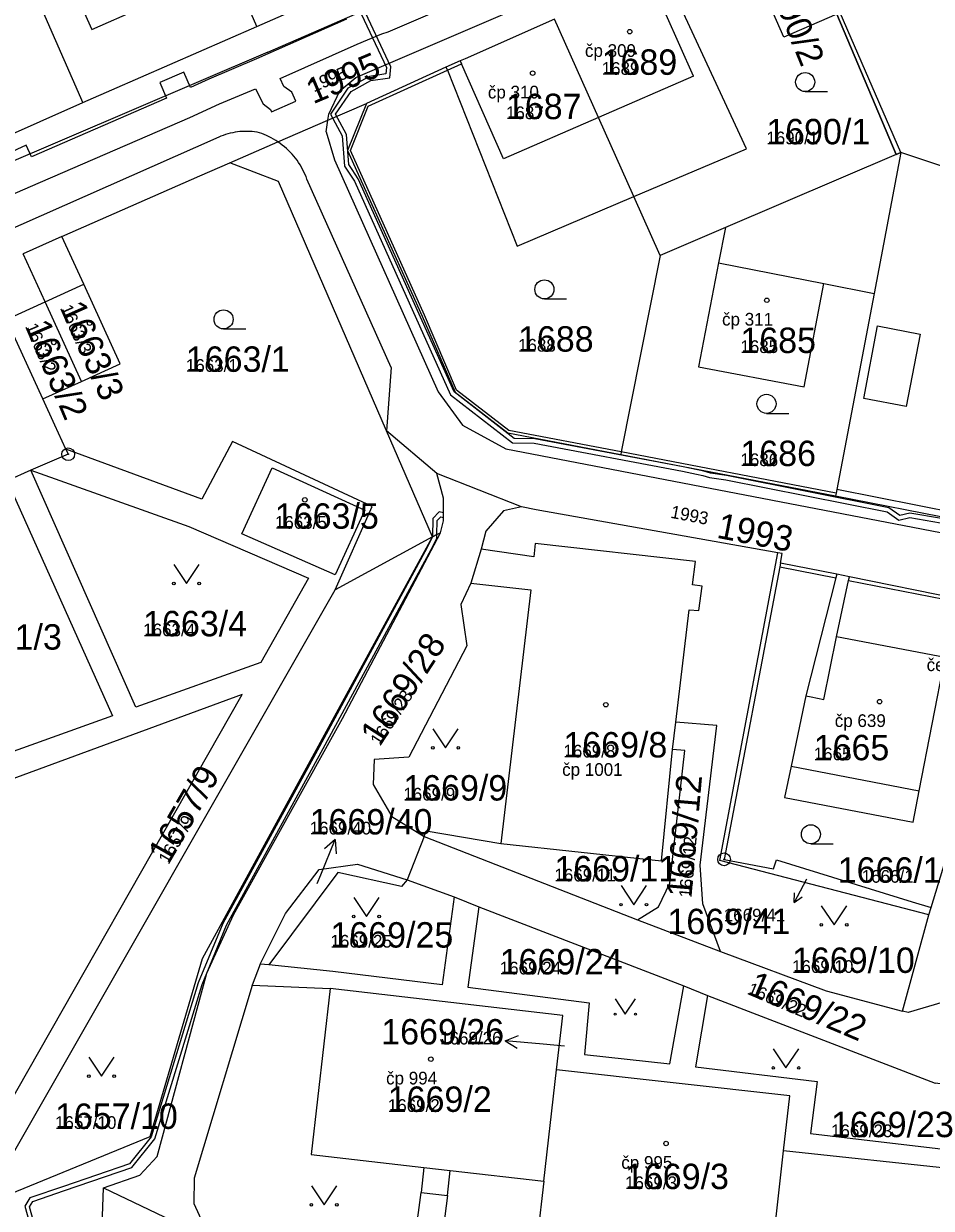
# Model space of a CAD drawing. Extents: x -763628 to -761565, y -976033 to -973833.
# Drawn here: x -762607.2 to -762535.7, y -975162.3 to -975069 of the extents above; entities that cross this region are included whole.
import ezdxf

# ---------------------------------------------------------------- set-up
doc = ezdxf.new("R2010")
doc.units = 0
for name, color, linetype in [('KN_cisla parcel 1000', 7, 'Continuous'), ('KN_cisla parcel 500', 7, 'Continuous'), ('KN_cisla parcel znacky', 7, 'Continuous'), ('KN_cisla popisna 500', 7, 'Continuous'), ('KN_hranice parcel', 7, 'Continuous'), ('KN_vecna bremena', 7, 'Continuous'), ('KN_vnitrni kresba parcel', 7, 'Continuous'), ('KN_znacky bodu BP', 7, 'Continuous'), ('KN_znacky budov', 7, 'Continuous'), ('KN_znacky kultur', 7, 'Continuous')]:
    doc.layers.add(name, color=color, linetype=linetype)

msp = doc.modelspace()

# ---------------------------------------------------------------- linework, layer by layer
at = {"layer": 'KN_cisla parcel znacky'}
for p, q in [((-762583.77, -975136.04), (-762582.646, -975133.258)), ((-762582.646, -975133.258), (-762583.485, -975133.998)), ((-762582.646, -975133.258), (-762582.557, -975134.374)), ((-762584.05, -975136.72), (-762583.77, -975136.04)), ((-762545.56, -975136.44), (-762546.504, -975138.215)), ((-762545.55, -975136.38), (-762545.56, -975136.44)), ((-762546.504, -975138.215), (-762546.485, -975137.465)), ((-762546.504, -975138.215), (-762545.893, -975137.78)), ((-762569.26, -975149.098), (-762568.218, -975148.687)), ((-762566.27, -975149.36), (-762569.26, -975149.098)), ((-762569.26, -975149.098), (-762568.306, -975149.685)), ((-762564.58, -975149.52), (-762566.27, -975149.36))]:
    msp.add_line(p, q, dxfattribs=at)
at = {"layer": 'KN_hranice parcel'}
for p, q in [((-762588.8, -975069.25), (-762599.99, -975043.58)), ((-762588.8, -975069.25), (-762572.25, -975062)), ((-762538.48, -975079.34), (-762543.16, -975068.29)), ((-762602.49, -975075.24), (-762588.8, -975069.25)), ((-762573.92, -975072.46), (-762580.18, -975075.31)), ((-762620.3, -975083.16), (-762602.49, -975075.24)), ((-762538.48, -975079.34), (-762551.93, -975085.09)), ((-762538.11, -975079.18), (-762540.22, -975090.27)), ((-762538.11, -975079.18), (-762538.48, -975079.34)), ((-762527.5, -975082.74), (-762538.11, -975079.18)), ((-762587.09, -975081.47), (-762590.94, -975079.99)), ((-762578.59, -975101.09), (-762587.09, -975081.47)), ((-762557.07, -975087.28), (-762559.14, -975082.65)), ((-762551.93, -975085.09), (-762557.07, -975087.28)), ((-762604.14, -975085.78), (-762607.19, -975087.14)), ((-762605.64, -975098.58), (-762602.6, -975097.19)), ((-762574.63, -975104.45), (-762578.59, -975101.09)), ((-762560.17, -975102.94), (-762543.26, -975106.2)), ((-762567.98, -975107.06), (-762574.63, -975104.45)), ((-762543.26, -975106.2), (-762527.46, -975109.33)), ((-762574.98, -975109.43), (-762582.65, -975113.61)), ((-762574.36, -975109.12), (-762574.98, -975109.43)), ((-762571.14, -975110.39), (-762571.95, -975113.09)), ((-762543.17, -975112.38), (-762547.58, -975111.51)), ((-762542.17, -975112.58), (-762543.17, -975112.38)), ((-762532.74, -975114.51), (-762542.17, -975112.58)), ((-762556.1, -975126.16), (-762555.82, -975124.01)), ((-762535.74, -975138.61), (-762532.33, -975127.36)), ((-762575.64, -975133.02), (-762576.98, -975136.42)), ((-762575.64, -975133.02), (-762558.84, -975139.58)), ((-762576.98, -975136.42), (-762573.28, -975137.78)), ((-762573.28, -975137.78), (-762571.34, -975138.57)), ((-762571.34, -975138.57), (-762555.21, -975144.77)), ((-762538, -975146.76), (-762535.92, -975139.19)), ((-762535.92, -975139.19), (-762535.74, -975138.61)), ((-762558.84, -975139.58), (-762552.31, -975142.08)), ((-762588.53, -975143.06), (-762589.17, -975144.72)), ((-762587.87, -975143.13), (-762588.53, -975143.06)), ((-762589.17, -975144.72), (-762583.02, -975145)), ((-762555.21, -975144.77), (-762553.34, -975145.55)), ((-762553.34, -975145.55), (-762535.42, -975152.45)), ((-762566.23, -975160.16), (-762565.22, -975151.39)), ((-762548.34, -975166.58), (-762547.35, -975157.76)), ((-762528.85, -975159.77), (-762547.35, -975157.76)), ((-762601.07, -975165.85), (-762600.86, -975160.68)), ((-762600.86, -975160.68), (-762591.67, -975165.07)), ((-762577.47, -975173.2), (-762575.87, -975161.05)), ((-762575.87, -975161.05), (-762573.8, -975161.29))]:
    msp.add_line(p, q, dxfattribs=at)
for points in [[(-762602.49, -975075.24), (-762602.65, -975074.88), (-762615.7, -975045.16)], [(-762594.38, -975066.21), (-762597.89, -975058.78), (-762599.15, -975056.11), (-762606.37, -975059.33), (-762605.03, -975062.29), (-762604.38, -975063.72), (-762605.61, -975064.27), (-762604.97, -975065.69), (-762604.22, -975067.35), (-762602.99, -975066.8), (-762601.78, -975069.49), (-762594.38, -975066.21)], [(-762543.16, -975068.29), (-762547.34, -975070.1), (-762549.45, -975065.25), (-762550.63, -975065.76), (-762551.03, -975064.81), (-762549.86, -975064.3), (-762550.64, -975062.55), (-762550.74, -975062.32)], [(-762559.14, -975082.65), (-762550.28, -975078.88), (-762555.4, -975067.8), (-762554.75, -975067.51), (-762555.94, -975064.83), (-762556.04, -975064.6)], [(-762565.38, -975068.69), (-762572.42, -975071.8), (-762572.79, -975071.96), (-762573.92, -975072.46)], [(-762559.14, -975082.65), (-762561.92, -975076.42), (-762565.38, -975068.69)], [(-762573.92, -975072.46), (-762573.81, -975072.69), (-762568.32, -975086.56), (-762559.14, -975082.65)], [(-762590.94, -975079.99), (-762587.14, -975078.34), (-762583.21, -975076.63), (-762580.18, -975075.31)], [(-762580.18, -975075.31), (-762581.66, -975079.03), (-762575.79, -975092.06), (-762573.2, -975098.04), (-762569.06, -975101.24), (-762560.17, -975102.94)], [(-762604.14, -975085.78), (-762593.28, -975081), (-762590.94, -975079.99)], [(-762551.93, -975085.09), (-762552.47, -975087.86), (-762554.05, -975096.04), (-762545.74, -975097.63), (-762544.18, -975089.49), (-762540.22, -975090.27)], [(-762602.6, -975097.19), (-762599.56, -975095.8), (-762602.42, -975089.55), (-762604.14, -975085.78)], [(-762602.6, -975097.19), (-762605.46, -975090.94), (-762607.19, -975087.14)], [(-762557.07, -975087.28), (-762560.13, -975102.74), (-762560.17, -975102.94)], [(-762605.64, -975098.58), (-762608.5, -975092.33), (-762610.25, -975088.49)], [(-762540.22, -975090.27), (-762543.17, -975105.71), (-762543.22, -975106), (-762543.26, -975106.2)], [(-762603.83, -975102.53), (-762604.7, -975100.63), (-762605.64, -975098.58)], [(-762582.65, -975113.61), (-762579.74, -975107.03), (-762590.71, -975101.93), (-762593.12, -975106.47), (-762603.83, -975102.53)], [(-762603.83, -975102.53), (-762603.65, -975102.93), (-762606.58, -975104.18), (-762608.46, -975105.01)], [(-762606.58, -975104.18), (-762594.16, -975108.62), (-762584.74, -975112.69), (-762588.48, -975119.33), (-762598.32, -975122.84), (-762606.58, -975104.18)], [(-762589.98, -975109.2), (-762587.6, -975103.99), (-762580.31, -975107.33), (-762582.63, -975112.43), (-762589.98, -975109.2)], [(-762574.36, -975109.12), (-762574.11, -975108.17), (-762574.12, -975106.38), (-762574.63, -975104.45)], [(-762608.46, -975105.01), (-762600.17, -975123.53), (-762610.99, -975127.4), (-762612.67, -975125.75)], [(-762567.98, -975107.06), (-762569.4, -975107.38), (-762570.77, -975108.98), (-762571.14, -975110.39)], [(-762547.79, -975110.69), (-762566.82, -975107.3), (-762567.98, -975107.06)], [(-762632.68, -975171.16), (-762632.45, -975171.07), (-762627.1, -975168.88), (-762597.19, -975156.63), (-762593.08, -975142.62), (-762574.98, -975109.43)], [(-762600.86, -975160.68), (-762598.01, -975159.67), (-762596.66, -975158.21), (-762592.74, -975143.77), (-762590.64, -975139.19), (-762582.07, -975123.74), (-762574.36, -975109.12)], [(-762555.82, -975124.01), (-762554.78, -975115.18), (-762554.02, -975115.23), (-762553.76, -975113.32), (-762554.53, -975113.22), (-762554.29, -975111.37), (-762566.89, -975109.96), (-762567.01, -975111.01), (-762571.14, -975110.39)], [(-762535.92, -975139.19), (-762552.37, -975134.92), (-762547.79, -975110.69)], [(-762547.58, -975111.51), (-762547.47, -975110.75), (-762547.79, -975110.69)], [(-762547.58, -975111.51), (-762547.64, -975111.8), (-762552.03, -975134.82), (-762548.14, -975135.56), (-762547.92, -975134.87), (-762537.22, -975138.16), (-762535.74, -975138.61)], [(-762571.95, -975113.09), (-762572.74, -975114.76), (-762572.29, -975118.02), (-762576.83, -975126.78), (-762579.56, -975126.96), (-762579.64, -975128.92), (-762578.18, -975131.45), (-762575.64, -975133.02)], [(-762571.95, -975113.09), (-762567.23, -975113.59), (-762569.61, -975133.56)], [(-762543.17, -975112.38), (-762543.24, -975112.67), (-762545.61, -975121.95), (-762546.76, -975127.48), (-762547.27, -975129.94), (-762537.16, -975131.9), (-762536.68, -975129.43), (-762534.63, -975118.92), (-762543.18, -975117.3), (-762542.23, -975112.87), (-762542.17, -975112.58)], [(-762634.24, -975155.87), (-762623.43, -975164.98), (-762608.7, -975159.22), (-762582.65, -975113.61)], [(-762632.02, -975155.16), (-762623.17, -975162.78), (-762610.31, -975157.57), (-762589.96, -975121.84), (-762614.1, -975130.7)], [(-762552.31, -975142.08), (-762553.7, -975138.33), (-762553.91, -975135.28), (-762552.59, -975124.29), (-762555.82, -975124.01)], [(-762569.61, -975133.56), (-762556.95, -975134.95), (-762556.1, -975126.16)], [(-762558.84, -975139.58), (-762557.19, -975138.56), (-762556.3, -975136.7), (-762555.12, -975126.25), (-762556.1, -975126.16)], [(-762519.59, -975130.51), (-762520.25, -975132.74), (-762532.03, -975144.17), (-762534.8, -975146.05), (-762537.54, -975146.88), (-762538, -975146.76)], [(-762575.64, -975133.02), (-762575.48, -975132.58), (-762569.61, -975133.56)], [(-762588.53, -975143.06), (-762586.54, -975139.09), (-762583.91, -975135.61), (-762580.88, -975135.21), (-762576.98, -975136.42)], [(-762576.98, -975136.42), (-762577.41, -975136.95), (-762582.42, -975135.86), (-762587.87, -975143.13)], [(-762573.28, -975137.78), (-762574.23, -975144.7), (-762582.82, -975143.64), (-762587.87, -975143.13)], [(-762571.34, -975138.57), (-762572.21, -975144.89), (-762562.66, -975146.11), (-762563.03, -975150.18), (-762556.3, -975150.93), (-762555.21, -975144.77)], [(-762552.31, -975142.08), (-762544.01, -975145.16), (-762538, -975146.76)], [(-762589.17, -975144.72), (-762589.25, -975145.02), (-762593.73, -975159.93), (-762593.75, -975161.9), (-762592.76, -975164.08)], [(-762583.02, -975145), (-762584.52, -975158.06), (-762575.65, -975159.08), (-762575.87, -975161.05)], [(-762565.22, -975151.39), (-762564.73, -975147.1), (-762583.02, -975145)], [(-762553.34, -975145.55), (-762554.27, -975151.16), (-762544.7, -975152.32), (-762545.22, -975156.41), (-762533.42, -975157.8), (-762532.89, -975152.76), (-762535.42, -975152.45)], [(-762547.35, -975157.76), (-762546.87, -975153.44), (-762565.22, -975151.39)], [(-762573.8, -975161.29), (-762573.58, -975159.32), (-762566.23, -975160.16)], [(-762566.23, -975160.16), (-762566.72, -975164.45), (-762557.8, -975165.48), (-762558.03, -975167.47)], [(-762573.8, -975161.29), (-762575.18, -975172.07), (-762559.12, -975179), (-762558.03, -975167.47)]]:
    msp.add_lwpolyline(points, dxfattribs=at)
at = {"layer": 'KN_vecna bremena'}
for points in [[(-762546.26, -975060.4), (-762546.52, -975060.51), (-762546.42, -975060.74), (-762543.16, -975068.29), (-762538.48, -975079.34), (-762538.11, -975079.18), (-762542.89, -975068.17), (-762546.16, -975060.63)], [(-762574.64, -975109.26), (-762574.62, -975108.14), (-762574.33, -975107.85), (-762574.11, -975107.9), (-762574.11, -975107.55), (-762574.45, -975107.47), (-762574.96, -975108), (-762574.98, -975109.43)], [(-762605.5, -975167.74), (-762605.18, -975167.61), (-762606.69, -975162.17), (-762606.44, -975161.75), (-762603.93, -975160.9), (-762598.63, -975159.07), (-762596.82, -975156.83), (-762593.1, -975144.67), (-762592.74, -975143.77), (-762591.18, -975140.01), (-762583.58, -975126.09), (-762575.09, -975110.43), (-762574.64, -975109.53), (-762574.64, -975109.26), (-762574.98, -975109.43), (-762575.39, -975110.27), (-762583.88, -975125.93), (-762591.48, -975139.87), (-762593.42, -975144.55), (-762597.12, -975156.67), (-762598.83, -975158.79), (-762604.03, -975160.58), (-762606.66, -975161.47), (-762607.05, -975162.13)]]:
    msp.add_lwpolyline(points, close=True, dxfattribs=at)
for points in [[(-762620.32, -975087.8), (-762606.61, -975081.85), (-762594.08, -975076.41), (-762591.74, -975075.34), (-762588.91, -975074.16), (-762588.31, -975075.35), (-762587.72, -975075.79), (-762587.64, -975075.98), (-762585.73, -975075.14), (-762586.04, -975074.43), (-762586.67, -975073.97), (-762586.98, -975073.34), (-762580.9, -975070.65), (-762578.97, -975069.83), (-762578.46, -975069.68), (-762568.97, -975065.59)], [(-762580.79, -975067.8), (-762578.61, -975072.48), (-762578.66, -975072.99), (-762579.95, -975073.2), (-762581.63, -975074.1), (-762583, -975076.15), (-762582.1, -975077.87), (-762581.91, -975080.25), (-762581.58, -975080.72), (-762581.12, -975081.42), (-762573.56, -975098.24), (-762568.68, -975102.03)], [(-762539.06, -975107.14), (-762551.84, -975104.6), (-762553.09, -975104.42), (-762553.62, -975104.27), (-762554.13, -975104.15), (-762555.24, -975103.92), (-762566.93, -975101.72), (-762568.56, -975101.69), (-762573.28, -975098.02), (-762580.82, -975081.26), (-762581.3, -975080.52), (-762581.57, -975080.13), (-762581.76, -975077.77), (-762582.6, -975076.17), (-762581.39, -975074.36), (-762579.83, -975073.52), (-762578.34, -975073.29), (-762578.27, -975072.42), (-762580.43, -975067.78)], [(-762581.76, -975068.67), (-762588.83, -975071.79), (-762592.58, -975073.4), (-762594.03, -975074.06), (-762594.56, -975072.84), (-762596.44, -975073.66), (-762595.9, -975074.9), (-762606.53, -975079.51), (-762606.95, -975078.6), (-762608.81, -975079.46)], [(-762568.68, -975102.03), (-762566.97, -975102.06), (-762555.3, -975104.26), (-762554.21, -975104.49), (-762553.7, -975104.59), (-762553.17, -975104.76), (-762551.9, -975104.94), (-762539.2, -975107.46), (-762538.28, -975108.11), (-762537.41, -975107.92), (-762534.99, -975108.32)], [(-762534.93, -975107.98), (-762537.41, -975107.58), (-762538.2, -975107.75), (-762539.06, -975107.14)]]:
    msp.add_lwpolyline(points, dxfattribs=at)
at = {"layer": 'KN_vnitrni kresba parcel'}
for p, q in [((-762587.93, -975071.28), (-762528.01, -975045.1)), ((-762581, -975073.28), (-762530.07, -975051.35)), ((-762554.43, -975073.16), (-762556.6, -975068.35)), ((-762587.93, -975071.28), (-762619.58, -975084.8)), ((-762573.81, -975072.69), (-762572.69, -975072.19)), ((-762572.79, -975071.96), (-762572.69, -975072.19)), ((-762569.39, -975079.68), (-762572.69, -975072.19)), ((-762580.05, -975075.52), (-762573.81, -975072.69)), ((-762554.43, -975073.16), (-762561.92, -975076.42)), ((-762582.27, -975074.33), (-762581, -975073.28)), ((-762583.14, -975076.15), (-762582.27, -975074.33)), ((-762581.44, -975079.03), (-762580.05, -975075.52)), ((-762583.34, -975077.54), (-762583.21, -975076.63)), ((-762583.21, -975076.63), (-762583.14, -975076.15)), ((-762561.92, -975076.42), (-762569.39, -975079.68)), ((-762583.34, -975077.54), (-762582.7, -975079.74)), ((-762591.8, -975077.98), (-762691.91, -975122.23)), ((-762575.61, -975091.98), (-762581.44, -975079.03)), ((-762582.7, -975079.74), (-762574.53, -975098.02)), ((-762578.22, -975096.1), (-762584.86, -975081.27)), ((-762552.47, -975087.86), (-762544.18, -975089.49)), ((-762605.46, -975090.94), (-762602.42, -975089.55)), ((-762608.5, -975092.33), (-762605.46, -975090.94)), ((-762573.08, -975097.88), (-762575.61, -975091.98)), ((-762541.04, -975098.53), (-762539.95, -975092.83)), ((-762539.95, -975092.83), (-762536.6, -975093.47)), ((-762536.6, -975093.47), (-762537.69, -975099.16)), ((-762578.22, -975096.1), (-762578.59, -975101.09)), ((-762574.53, -975098.02), (-762572.61, -975100.65)), ((-762568.98, -975101.06), (-762573.08, -975097.88)), ((-762537.69, -975099.16), (-762541.04, -975098.53)), ((-762574.98, -975109.43), (-762578.59, -975101.09)), ((-762572.61, -975100.65), (-762569.22, -975102.51)), ((-762560.13, -975102.74), (-762568.98, -975101.06)), ((-762569.22, -975102.51), (-762527.62, -975110.52)), ((-762543.22, -975106), (-762560.13, -975102.74)), ((-762527.32, -975108.85), (-762543.17, -975105.71)), ((-762547.64, -975111.8), (-762543.24, -975112.67)), ((-762542.23, -975112.87), (-762532.78, -975114.72)), ((-762544.17, -975122.24), (-762543.18, -975117.3)), ((-762545.61, -975121.95), (-762545.19, -975122.03)), ((-762545.19, -975122.03), (-762544.17, -975122.24)), ((-762546.76, -975127.48), (-762536.68, -975129.43)), ((-762575.65, -975159.08), (-762573.58, -975159.32))]:
    msp.add_line(p, q, dxfattribs=at)
for points in [[(-762588.6, -975077.62), (-762588.789, -975077.584), (-762588.98, -975077.554), (-762589.171, -975077.532), (-762589.363, -975077.518), (-762589.556, -975077.51), (-762589.749, -975077.51), (-762589.941, -975077.517), (-762590.133, -975077.531), (-762590.325, -975077.553), (-762590.515, -975077.582), (-762590.705, -975077.617), (-762590.892, -975077.66), (-762591.079, -975077.711), (-762591.263, -975077.768), (-762591.444, -975077.832), (-762591.624, -975077.902), (-762591.8, -975077.98)], [(-762587.14, -975078.34), (-762587.311, -975078.229), (-762587.486, -975078.124), (-762587.665, -975078.025), (-762587.846, -975077.932), (-762588.031, -975077.845), (-762588.218, -975077.764), (-762588.408, -975077.689), (-762588.6, -975077.62)], [(-762584.86, -975081.27), (-762584.934, -975081.074), (-762585.015, -975080.88), (-762585.103, -975080.69), (-762585.198, -975080.503), (-762585.299, -975080.319), (-762585.406, -975080.139), (-762585.52, -975079.963), (-762585.64, -975079.791), (-762585.766, -975079.623), (-762585.897, -975079.46), (-762586.035, -975079.301), (-762586.178, -975079.147), (-762586.326, -975078.999), (-762586.479, -975078.856), (-762586.638, -975078.718), (-762586.801, -975078.586), (-762586.968, -975078.46), (-762587.14, -975078.34)]]:
    msp.add_lwpolyline(points, dxfattribs=at)
at = {"layer": 'KN_znacky bodu BP'}
for centre, radius in [((-762603.65, -975102.93), 0.5), ((-762603.65, -975102.93), 0.0303), ((-762552.03, -975134.82), 0.5), ((-762552.03, -975134.82), 0.0303)]:
    msp.add_circle(centre, radius, dxfattribs=at)
at = {"layer": 'KN_znacky budov'}
for centre in [(-762559.457, -975069.659), (-762567.097, -975072.929), (-762548.667, -975090.809), (-762601.967, -975092.609), (-762604.787, -975094.129), (-762585.027, -975106.519), (-762561.337, -975122.649), (-762539.797, -975122.409), (-762575.107, -975150.549), (-762556.597, -975157.189)]:
    msp.add_circle(centre, 0.175, dxfattribs=at)
at = {"layer": 'KN_znacky kultur'}
for p, q in [((-762545.653, -975074.38), (-762543.903, -975074.38)), ((-762566.173, -975090.7), (-762564.423, -975090.7)), ((-762591.423, -975093.06), (-762589.673, -975093.06)), ((-762548.693, -975099.71), (-762546.943, -975099.71)), ((-762545.203, -975133.6), (-762543.453, -975133.6))]:
    msp.add_line(p, q, dxfattribs=at)
for points in [[(-762595.34, -975111.609), (-762594.34, -975113.11), (-762593.34, -975111.609)], [(-762574.95, -975124.539), (-762573.95, -975126.04), (-762572.95, -975124.539)], [(-762560.14, -975136.889), (-762559.14, -975138.39), (-762558.14, -975136.889)], [(-762581.18, -975137.819), (-762580.18, -975139.32), (-762579.18, -975137.819)], [(-762544.38, -975138.479), (-762543.38, -975139.98), (-762542.38, -975138.479)], [(-762560.61, -975145.799), (-762559.81, -975147), (-762559.01, -975145.799)], [(-762602.03, -975150.389), (-762601.03, -975151.89), (-762600.03, -975150.389)], [(-762548.16, -975149.739), (-762547.16, -975151.24), (-762546.16, -975149.739)], [(-762584.51, -975160.519), (-762583.51, -975162.02), (-762582.51, -975160.519)]]:
    msp.add_lwpolyline(points, dxfattribs=at)
for centre, radius in [((-762545.653, -975073.63), 0.75), ((-762566.173, -975089.95), 0.75), ((-762591.423, -975092.31), 0.75), ((-762548.693, -975098.96), 0.75), ((-762595.34, -975113.109), 0.1), ((-762593.34, -975113.109), 0.1), ((-762574.95, -975126.039), 0.1), ((-762572.95, -975126.039), 0.1), ((-762545.203, -975132.85), 0.75), ((-762560.14, -975138.389), 0.1), ((-762558.14, -975138.389), 0.1), ((-762581.18, -975139.319), 0.1), ((-762579.18, -975139.319), 0.1), ((-762544.38, -975139.979), 0.1), ((-762542.38, -975139.979), 0.1), ((-762560.61, -975147), 0.08), ((-762559.01, -975147), 0.08), ((-762548.16, -975151.239), 0.1), ((-762546.16, -975151.239), 0.1), ((-762602.03, -975151.889), 0.1), ((-762600.03, -975151.889), 0.1), ((-762584.51, -975162.019), 0.1), ((-762582.51, -975162.019), 0.1)]:
    msp.add_circle(centre, radius, dxfattribs=at)

# ---------------------------------------------------------------- texts
at = {"layer": 'KN_cisla parcel 1000'}
for s, rotation, p in [('1690/2', 292, (-762548.99, -975064.953)), ('1995', 23, (-762584.377, -975075.392)), ('1663/3', 294, (-762604.314, -975091.412)), ('1663/2', 293, (-762607.059, -975092.86)), ('1993', 349, (-762552.682, -975109.494)), ('1669/28', 57, (-762579.107, -975125.962)), ('1657/9', 60, (-762595.746, -975135.27)), ('1669/12', 85, (-762554.601, -975137.866)), ('1669/22', 337, (-762550.282, -975145.396))]:
    msp.add_text(s, height=2, rotation=rotation, dxfattribs=at).set_placement(p)
for s, p in [('1689', (-762561.67, -975073.06)), ('1687', (-762569.2, -975076.55)), ('1690/1', (-762548.71, -975078.53)), ('1688', (-762568.25, -975094.85)), ('1685', (-762550.75, -975094.96)), ('1663/1', (-762594.39, -975096.44)), ('1686', (-762550.75, -975103.86)), ('1663/5', (-762587.384, -975108.792)), ('1663/4', (-762597.75, -975117.26)), ('1661/3', (-762612.33, -975118.31)), ('1669/8', (-762564.68, -975126.8)), ('1665', (-762544.98, -975127.02)), ('1669/9', (-762577.28, -975130.19)), ('1669/40', (-762584.649, -975132.861)), ('1669/11', (-762565.389, -975136.557)), ('1666/1', (-762543.087, -975136.66)), ('1669/41', (-762556.491, -975140.709)), ('1669/25', (-762583.011, -975141.766)), ('1669/24', (-762569.693, -975143.878)), ('1669/10', (-762546.69, -975143.76)), ('1669/26', (-762579.013, -975149.392)), ('1669/2', (-762578.5, -975154.7)), ('1657/10', (-762604.69, -975156.04)), ('1669/23', (-762543.62, -975156.69)), ('1669/3', (-762559.83, -975160.78))]:
    msp.add_text(s, height=2, dxfattribs=at).set_placement(p)
at = {"layer": 'KN_cisla parcel 500'}
for s, p in [('1689', (-762561.67, -975073.06)), ('1687', (-762569.2, -975076.55)), ('1690/1', (-762548.71, -975078.53)), ('1688', (-762568.25, -975094.85)), ('1685', (-762550.75, -975094.96)), ('1663/1', (-762594.39, -975096.44)), ('1686', (-762550.75, -975103.86)), ('1663/5', (-762587.384, -975108.792)), ('1663/4', (-762597.75, -975117.26)), ('1669/8', (-762564.68, -975126.8)), ('1665', (-762544.98, -975127.02)), ('1669/9', (-762577.28, -975130.19)), ('1669/40', (-762584.649, -975132.861)), ('1669/11', (-762565.389, -975136.557)), ('1666/1', (-762541.204, -975136.66)), ('1669/41', (-762552.057, -975139.709)), ('1669/25', (-762583.011, -975141.766)), ('1669/24', (-762569.693, -975143.878)), ('1669/10', (-762546.69, -975143.76)), ('1669/26', (-762574.379, -975149.392)), ('1669/2', (-762578.5, -975154.7)), ('1657/10', (-762604.69, -975156.04)), ('1669/23', (-762543.62, -975156.69)), ('1669/3', (-762559.83, -975160.78))]:
    msp.add_text(s, height=1, dxfattribs=at).set_placement(p)
for s, rotation, p in [('1995', 23, (-762584.319, -975074.446)), ('1663/3', 294, (-762604.314, -975091.412)), ('1663/2', 293, (-762607.059, -975092.86)), ('1993', 349, (-762556.299, -975107.922)), ('1669/28', 57, (-762579.107, -975125.962)), ('1657/9', 60, (-762595.746, -975135.27)), ('1669/12', 85, (-762554.601, -975137.866)), ('1669/22', 337, (-762550.282, -975145.396))]:
    msp.add_text(s, height=1, rotation=rotation, dxfattribs=at).set_placement(p)
at = {"layer": 'KN_cisla popisna 500'}
for s, p in [('čp 309', (-762562.981, -975071.651)), ('čp 310', (-762570.621, -975074.921)), ('čp 311', (-762552.191, -975092.801)), ('če 6180', (-762536.091, -975120.001)), ('čp 639', (-762543.321, -975124.401)), ('čp 1001', (-762564.774, -975128.247)), ('čp 994', (-762578.631, -975152.541)), ('čp 995', (-762560.121, -975159.181))]:
    msp.add_text(s, height=1, dxfattribs=at).set_placement(p)

doc.saveas('drawing.dxf')
